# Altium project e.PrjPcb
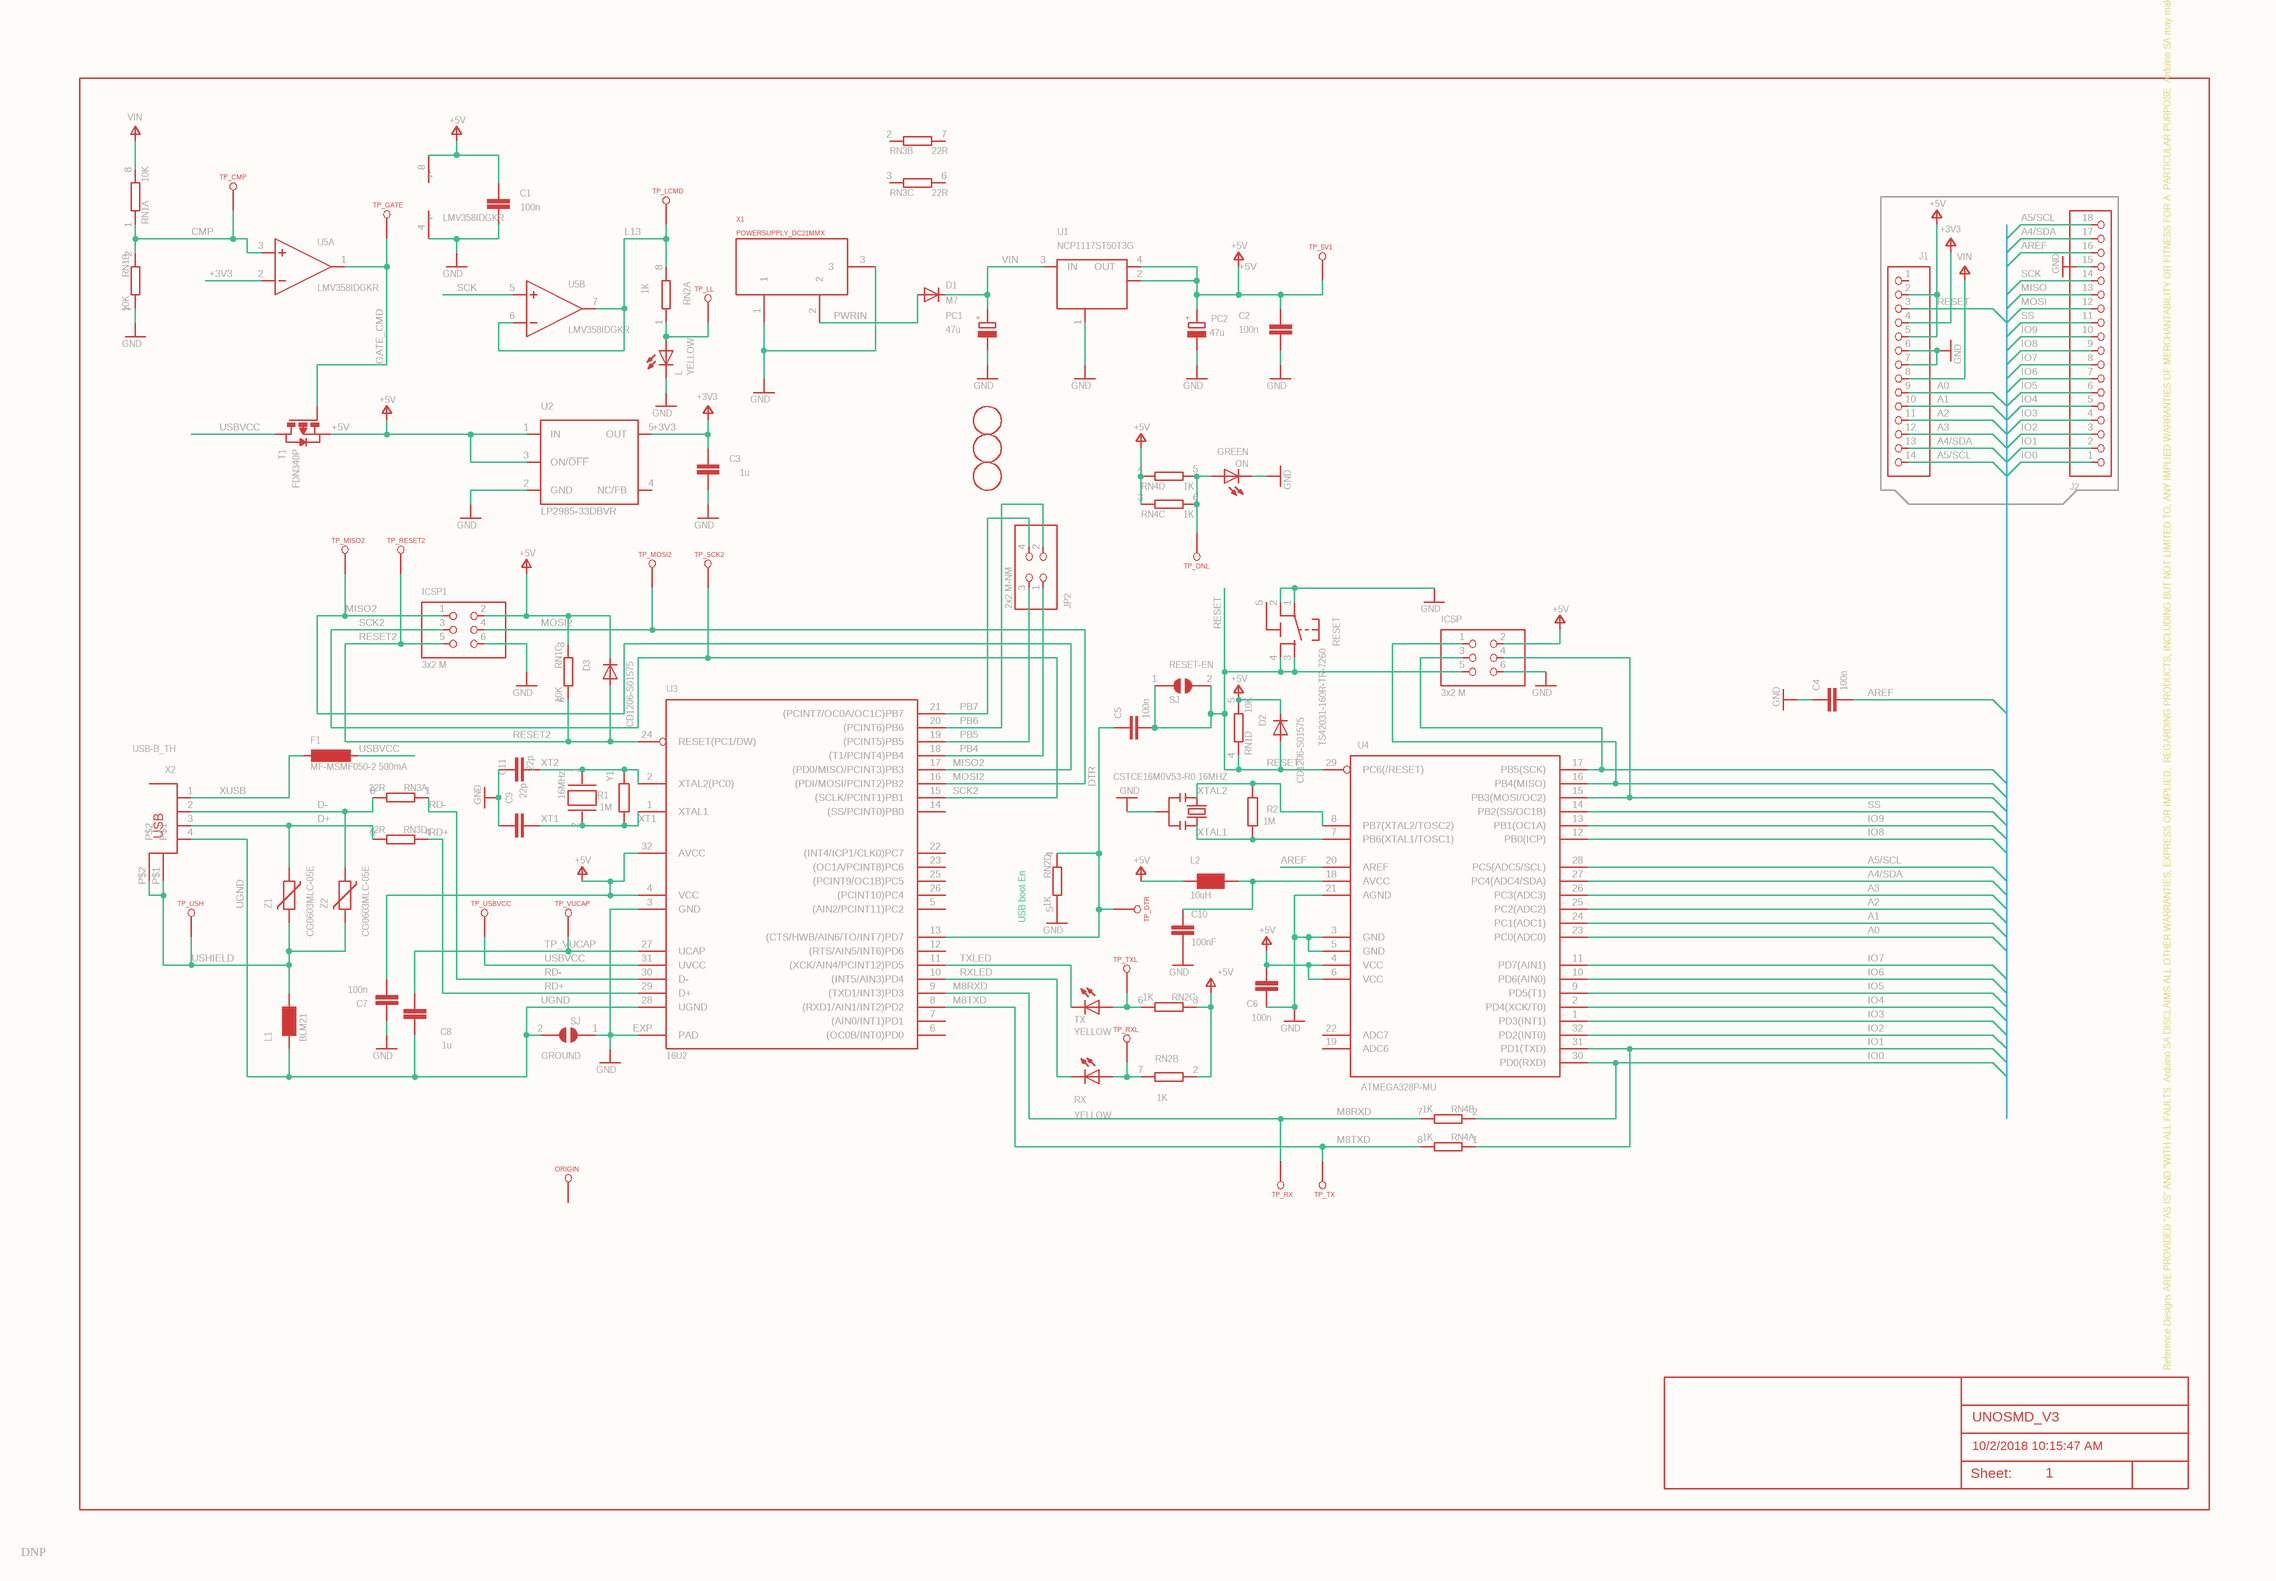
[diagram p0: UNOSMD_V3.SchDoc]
1 sheet, 111 parts. Net scope: global (net labels, ports and power ports of the same name join across sheets).
Board file: UNOSMD_V3.PcbDoc

## Sheet UNOSMD_V3.SchDoc: UNOSMD_V3
size 409 x 282 mm; Date: 10/2/2018 10:15:47 AM; SheetNumber: 1; Origin: Eagle; CODE-ARDUINO: DNP; GateName_1: G$1; SymbolName_1: A3L-LOC; DeviceName: -STANDARD; LibraryName: Arduino-utility; DeviceSetName: A3-FRAME; Sheet: Sheet:; ReferenceDesignsAREPROVIDED"ASIS"AND"WITHALLFAULTS.ArduinoSADISCLAIMSALLOTHERWARRANTIES,EXPRESSORIMPLIED,
REGARDINGPRODUCTS,INCLUDINGBUTNOTLIMITEDTO,ANYIMPLIEDWARRANTIESOFMERCHANTABILITYORFITNESSFORA
PARTICULARPURPOSE
ArduinoSAmaymakechangestospecificationsandproductdescriptionsatanytime,withoutnotice.TheCustomermustnot
relyontheabsenceorcharacteristicsofanyfeaturesorinstructionsmarked"reserved"or"undefined."ArduinoSAreserves
theseforfuturedefinitionandshallhavenoresponsibilitywhatsoeverforconflictsorincompatibilitiesarisingfromfuturechangestothem.
TheproductinformationontheWebSiteorMaterialsissubjecttochangewithoutnotice.Donotfinalizeadesignwiththisinfo

ARDUINOandotherArduinobrandsandlogosandTrademarksofArduinoSA.AllArduinoSATrademarkscannotbeusedwithoutowner'sformalpermission

Thisfileislicensedunder:CC-SA-BY-NC: Reference Designs ARE PROVIDED "AS IS" AND "WITH ALL FAULTS. Arduino SA DISCLAIMS ALL OTHER WARRANTIES, EXPRESS OR IMPLIED, / REGARDING PRODUCTS, INCLUDING BUT NOT LIMITED TO, ANY IMPLIED WARRANTIES OF MERCHANTABILITY OR FITNESS FOR A / PARTICULAR PURPOSE / Arduino SA may make changes to specifications and product descriptions at any time, without notice. The Customer must not / rely on the absence or characteristics of any features or instructions marked "reserved" or "undefined." Arduino SA reserves / these for future definition and shall have no responsibility whatsoever for conflicts or incompatibilities arising from future changes to them. / The product information on the Web Site or Materials is subject to change without notice. Do not finalize a design with this info / ARDUINO and other Arduino brands and logos and Trademarks of Arduino SA. All Arduino SA Trademarks cannot be used without owner's formal permission / This file is licensed under : CC-SA-BY-NC

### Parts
+3V1  +3V3
+3V2  +3V3
C1  100n  [C0603-ROUND]
C2  100n  [C0603-ROUND]
C3  1u  [C0603-ROUND]
C4  100n  [C0603-ROUND]
C5  100n  [C0603-ROUND]
C6  100n  [C0603-ROUND]
C7  100n  [C0603-ROUND]
C8  1u  [C0603-ROUND]
C9  22p  [C0603-ROUND]
C10  100nF  [C0603-ROUND]
C11  22p  [C0603-ROUND]
D1  M7  [SMB]
D2  CD1206-S01575  [MINIMELF]
D3  CD1206-S01575  [MINIMELF]
F1  MF-MSMF050-2 500mA  [L1812]
FD1  DNP  [FD-1-1.5]  (value not drawn)
FD2  DNP  [FD-1-1.5]  (value not drawn)
FD3  DNP  [FD-1-1.5]  (value not drawn)
GND1  GND
GND2  GND
GND3  GND
GND4  GND
GND5  GND
GND6  GND
GND7  GND
GND8  GND
GND9  GND
GND10  GND
GND11  GND
GND12  GND
GND13  GND
GND14  GND
GND15  GND
GND16  GND
GND17  GND
GND18  GND
GND19  GND
GND20  GND
GND21  GND
GND22  GND
GND23  GND
GND24  GND
GROUND  SJ  [SJ]
ICSP  3x2 M  [2X03]
ICSP1  3x2 M  [2X03]
J1  -  [1X14-CUSTOM]  (value not drawn)
J2  -  [1X18-CUSTOM]  (value not drawn)
JP2  2x2 M-NM  [2X02]
L  YELLOW  [CHIP-LED0805]
L1  BLM21  [0805]
L2  10uH  [0805]
ON  GREEN  [CHIP-LED0805]
ORIGIN  TP_SP  [TP-SP]  (value not drawn)
P+1  +5V  DATASHEET: DNP
P+2  +5V
P+3  +5V
P+5  +5V
P+6  +5V
P+7  +5V
P+8  +5V
P+9  +5V
P+10  +5V
P+11  +5V
P+12  +5V
P+13  +5V
PC1  47u  [PANASONIC_D]
PC2  47u  [PANASONIC_D]
R1  1M  [R0603-ROUND]
R2  1M  [R0603-ROUND]
RESET  TS42031-160R-TR-7260  [TS42]
RESET-EN  SJ  [SJ]
RN1  10K  [CAY16]  (parts A,B,C,D of 4)
RN2  1K  [CAY16]  (parts A,B,C,D of 4)
RN3  22R  [CAY16]  (parts A,B,C,D of 4)
RN4  1K  [CAY16]  (parts A,B,C,D of 4)
RX  YELLOW  [CHIP-LED0805]
T1  FDN340P  [SOT-23]
TP_5V1  TP_SP  [TP-SP]  (value not drawn)
TP_CMP  TP_SP  [TP-SP]  (value not drawn)
TP_DTR  TP_SP  [TP-SP]  (value not drawn)
TP_GATE  TP_SP  [TP-SP]  (value not drawn)
TP_LCMD  TP_SP  [TP-SP]  (value not drawn)
TP_LL  TP_SP  [TP-SP]  (value not drawn)
TP_MISO2  TP_SP  [TP-SP]  (value not drawn)
TP_MOSI2  TP_SP  [TP-SP]  (value not drawn)
TP_ONL  TP_SP  [TP-SP]  (value not drawn)
TP_RESET2  TP_SP  [TP-SP]  (value not drawn)
TP_RX  TP_SP  [TP-SP]  (value not drawn)
TP_RXL  TP_SP  [TP-SP]  (value not drawn)
TP_SCK2  TP_SP  [TP-SP]  (value not drawn)
TP_TX  TP_SP  [TP-SP]  (value not drawn)
TP_TXL  TP_SP  [TP-SP]  (value not drawn)
TP_USBVCC  TP_SP  [TP-SP]  (value not drawn)
TP_USH  TP_SP  [TP-SP]  (value not drawn)
TP_VUCAP  TP_SP  [TP-SP]  (value not drawn)
TX  YELLOW  [CHIP-LED0805]
U1  NCP1117ST50T3G  [SOT223]
U2  LP2985-33DBVR  [SOT23-DBV]
U3  16U2  [ATMEL_QFN32]
U4  ATMEGA328P-MU  [MLF32]
U5  LMV358IDGKR  [MSOP08]  (parts A,B,C of 3)
VIN1  VIN
VIN2  VIN
X1  POWERSUPPLY_DC21MMX  [POWERSUPPLY_DC-21MM]
X2  USB-B_TH  [PN61729]
Y1  16MHz  [QS]
Y2  CSTCE16M0V53-R0 16MHZ  [RESONATOR]
Z1  CG0603MLC-05E  [CT/CN0603]
Z2  CG0603MLC-05E  [CT/CN0603]

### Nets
+3V3: +3V1.?1(+3V3) C3.2 U2.5(OUT) U5.2(-IN)
+5V: C2.2 P+8.?1(+5V) P+10.?1(+5V) PC2.+ T1.2(S) TP_5V1.X(TESTP) U1.2(OUT) U1.4(OUT) U2.1(IN) U2.3(ON/~{OFF})
A0: J1.9 J2.6 U4.9(PD5(T1)) U4.23(PC0(ADC0))  [also labelled IO5]
A1: J1.10 J2.5 U4.2(PD4(XCK/T0)) U4.24(PC1(ADC1))  [also labelled IO4]
A2: J1.11 J2.4 U4.1(PD3(INT1)) U4.25(PC2(ADC2))  [also labelled IO3]
A3: J1.12 J2.3 U4.26(PC3(ADC3)) U4.32(PD2(INT0))  [also labelled IO2]
A4/SDA: J1.13 J2.2 J2.17 RN4.1 U4.27(PC4(ADC4/SDA)) U4.31(PD1(TXD))  [also labelled IO1]
A5/SCL: J1.14 J2.1 J2.18 RN4.2 U4.28(PC5(ADC5/SCL)) U4.30(PD0(RXD))  [also labelled IO0]
AREF: C4.2 J2.16 U4.20(AREF)
CMP: RN1.1 RN1.2 TP_CMP.X(TESTP) U5.3(+IN)
D+: RN3.5 X2.3 Z1.1
D-: RN3.8 X2.2 Z2.1
DTR: C5.1 RN2.4 TP_DTR.X(TESTP) U3.13((CTS/HWB/AIN6/TO/INT7)PD7)
GATE_CMD: T1.3(G) TP_GATE.X(TESTP) U5.1(OUT)
IO6: J2.7 U4.10(PD6(AIN0))
IO7: J2.8 U4.11(PD7(AIN1))
IO8: J2.9 U4.12(PB0(ICP))
IO9: J2.10 U4.13(PB1(OC1A))
L13: RN2.8 TP_LCMD.X(TESTP) U5.6(-IN) U5.7(OUT)
M8RXD: RN4.7 TP_RX.X(TESTP) U3.9((TXD1/INT3)PD3)
M8TXD: RN4.8 TP_TX.X(TESTP) U3.8((RXD1/AIN1/INT2)PD2)
MISO: J2.13
MISO2: ICSP1.1 TP_MISO2.X(TESTP) U3.17((PD0/MISO/PCINT3)PB3)
MOSI: C5.2 D2.A ICSP.5 J1.2 J1.3 J1.5 J2.12 P+13.?1(+5V) RESET.3 RESET.4 RESET-EN.1 RESET-EN.2 RN1.4 U4.29(PC6(/RESET))  [also labelled RESET]
MOSI2: ICSP1.4 TP_MOSI2.X(TESTP) U3.16((PDI/MOSI/PCINT2)PB2)
PB4: JP2.1 U3.18((T1/PCINT4)PB4)
PB5: JP2.3 U3.19((PCINT5)PB5)
PB6: JP2.2 U3.20((PCINT6)PB6)
PB7: JP2.4 U3.21((PCINT7/OC0A/OC1C)PB7)
PWRIN: D1.A X1.2
RD+: RN3.4 U3.29(D+)
RD-: RN3.1 U3.30(D-)
RESET2: D3.A ICSP1.5 RN1.6 TP_RESET2.X(TESTP) U3.24(RESET(PC1/DW))
RXLED: RX.C U3.10((INT5/AIN3)PD4)
SCK: J2.14 U5.5(+IN)
SCK2: ICSP1.3 TP_SCK2.X(TESTP) U3.15((SCLK/PCINT1)PB1)
SS: J2.11 U4.14(PB2(SS/OC1B))
TP_VUCAP: C8.1 TP_VUCAP.X(TESTP) U3.27(UCAP)
TXLED: TX.C U3.11((XCK/AIN4/PCINT12)PD5)
UGND: C8.2 GROUND.2 L1.1 U3.28(UGND) X2.4
USBVCC: F1.1 T1.1(D) TP_USBVCC.X(TESTP) U3.31(UVCC)
USHIELD: L1.2 TP_USH.X(TESTP) X2.P$1 X2.P$2 Z1.2 Z2.2
VIN: D1.C PC1.+ U1.3(IN)
XT1: C9.1 R1.1 U3.1(XTAL1) Y1.2
XT2: C11.1 R1.2 U3.2(XTAL2(PC0)) Y1.1
XTAL1: R2.1 U4.7(PB6(XTAL1/TOSC1)) Y2.3
XTAL2: R2.2 U4.8(PB7(XTAL2/TOSC2)) Y2.1
XUSB: F1.2 X2.1
Net+3V2_?1: +3V2.?1(+3V3) J1.4
NetC1_1: C1.1 GND18.?1(GND) U5.4(V-)
NetC1_2: C1.2 P+9.?1(+5V) U5.8(V+)
NetC2_1: C2.1 GND7.?1(GND)
NetC3_1: C3.1 GND21.?1(GND)
NetC4_1: C4.1 GND13.?1(GND)
NetC6_1: C6.1 GND2.?1(GND) U4.3(GND) U4.5(GND) U4.21(AGND)
NetC6_2: C6.2 P+12.?1(+5V) U4.4(VCC) U4.6(VCC)
NetC7_1: C7.1 P+6.?1(+5V) U3.4(VCC) U3.32(AVCC)
NetC7_2: C7.2 GND16.?1(GND)
NetC9_2: C9.2 C11.2 GND8.?1(GND)
NetC10_1: C10.1 L2.2 U4.18(AVCC)
NetC10_2: C10.2 GND24.?1(GND)
NetD2_C: D2.C P+2.?1(+5V) RN1.5
NetD3_C: D3.C ICSP1.2 P+11.?1(+5V) RN1.3
NetGND1_?1: GND1.?1(GND) ICSP.6
NetGND3_?1: GND3.?1(GND) Y2.2
NetGND4_?1: GND4.?1(GND) U2.2(GND)
NetGND5_?1: GND5.?1(GND) J2.15
NetGND6_?1: GND6.?1(GND) J1.6 J1.7
NetGND9_?1: GND9.?1(GND) PC1.-
NetGND10_?1: GND10.?1(GND) PC2.-
NetGND11_?1: GND11.?1(GND) U1.1(GND/ADJ)
NetGND12_?1: GND12.?1(GND) RESET.1 RESET.2
NetGND14_?1: GND14.?1(GND) ON.C
NetGND15_?1: GND15.?1(GND) RN2.5
NetGND17_?1: GND17.?1(GND) L.C
NetGND19_?1: GND19.?1(GND) X1.1 X1.3
NetGND20_?1: GND20.?1(GND) RN1.7
NetGND22_?1: GND22.?1(GND) ICSP1.6
NetGND23_?1: GND23.?1(GND) GROUND.1 U3.3(GND) U3.EXP(PAD)
NetICSP_1: ICSP.1 U4.16(PB4(MISO))
NetICSP_2: ICSP.2 P+1.?1(+5V)
NetICSP_3: ICSP.3 U4.17(PB5(SCK))
NetICSP_4: ICSP.4 U4.15(PB3(MOSI/OC2))
NetJ1_8: J1.8 VIN2.?1(VIN)
NetL2_1: L2.1 P+3.?1(+5V)
NetL_A: L.A RN2.1 TP_LL.X(TESTP)
NetON_A: ON.A RN4.5 RN4.6 TP_ONL.X(TESTP)
NetP+5_?1: P+5.?1(+5V) RN4.3 RN4.4
NetP+7_?1: P+7.?1(+5V) RN2.2 RN2.3
NetRN1_8: RN1.8 VIN1.?1(VIN)
NetRN2_6: RN2.6 TP_TXL.X(TESTP) TX.A
NetRN2_7: RN2.7 RX.A TP_RXL.X(TESTP)

Not connected (* = marked no-connect by the designer): J1 1; ORIGIN X(TESTP); RESET 5(5-GND); RN3 2(1) 3(1) 6(2) 7(2); U2 4(NC/FB); U3 5((AIN2/PCINT11)PC2) 6((OC0B/INT0)PD0) 7((AIN0/INT1)PD1) 12((RTS/AIN5/INT6)PD6) 14((SS/PCINT0)PB0) 22((INT4/ICP1/CLK0)PC7) 23((OC1A/PCINT8)PC6) 25((PCINT9/OC1B)PC5) 26((PCINT10)PC4); U4 19(ADC6) 22(ADC7)

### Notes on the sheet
- USB boot En
- Reference Designs ARE PROVIDED "AS IS" AND "WITH ALL FAULTS. Arduino SA DISCLAIMS ALL OTHER WARRANTIES, EXPRESS OR IMPLIED,
  REGARDING PRODUCTS, INCLUDING BUT NOT LIMITED TO, ANY IMPLIED WARRANTIES OF MERCHANTABILITY OR FITNESS FOR A
  PARTICULAR PURPOSE
  Arduino SA may make changes to specifications and product descriptions at any time, without notice. The Customer must not
  rely on the absence or characteristics of any features or instructions marked "reserved" or "undefined." Arduino SA reserves
  these for future definition and shall have no responsibility whatsoever for conflicts or incompatibilities arising from future changes to them.
  The product information on the Web Site or Materials is subject to change without notice. Do not finalize a design with this info
  ARDUINO and other Arduino brands and logos and Trademarks of Arduino SA. All Arduino SA Trademarks cannot be used without owner's formal permission
  This file is licensed under : CC-SA-BY-NC
- UNOSMD_V3
- 10/2/2018 10:15:47 AM
- Sheet:
- 1

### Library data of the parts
+3V1 +3V2 = +3V3: 3V3 symbol; MANUFACTURER: DNP; GateName_1: G$1
C1-C9 C11 = C-EU0603-RND: CAPACITOR, European symbol; GateName_1: G$1; SymbolName_1: C-EU
C10 = 0015_100NF_0603: 100nF 0603; GateName_1: G$1; SymbolName_1: C-EU; MONTHLY_USAGE: _____; TYPE: Condensatori
D1 = DIODE-SMB: DIODE; GateName_1: G$1; SymbolName_1: D; DeviceSetName: DIODE-
D2 D3 = DIODE-MINIMELF: DIODE; GateName_1: G$1; SymbolName_1: D; DeviceSetName: DIODE-
F1 = L-EUL1812: INDUCTOR, European symbol; GateName_1: G$1; SymbolName_1: L-EU
FD1-FD3 = FIDUCIAL-1.5MM: Fiducial mount; GateName_1: G$1; SymbolName_1: ARDUINO_FIDUCIAL; DeviceName: -1.5MM
GND1-GND15 GND18-GND24 = GND: GND symbol; MANUFACTURER: DNP; GateName_1: 1
GND16 GND17 = GND: SUPPLY SYMBOL; GateName_1: 1
GROUND RESET-EN = SJ: SMD solder JUMPER; GateName_1: 1
ICSP ICSP1 = PINHD-2X3: PIN HEADER; GateName_1: A; SymbolName_1: PINH2X3
J1 = PINHD-1X14-CUSTOM: PIN HEADER; GateName_1: A
J2 = PINHD-1X18: GateName_1: A
JP2 = PINHD-2X2: PIN HEADER; GateName_1: A; SymbolName_1: PINH2X2
L ON RX TX = LEDCHIP-LED0805: LED   OSRAM: - CHIPLED LG R971, LG N971, LY N971, LG Q971, LY Q971, LO R971, LY R971 LH N974, LH R974 LS Q976, LO Q976, LY Q976 LO Q996 - Hyper CHIPLED LW Q18S LB Q993, LB Q99A, LB R99A - SideLED LS A670, LO A670, LY A670, LG A670, LP A670 LB A673, LV A673, LT A673, LW A673 LH A674 LY A675 LS A676, LA A676, LO A676, LY A676, LW A676 LS A679, LY A679, LG A679 -  Hyper Micro SIDELEDÂ® LS Y876, LA Y876, LO Y876, LY Y876 LT Y87S - SmartLED LW L88C, LW L88S LB L89C, LB L89S, LG L890 LS L89K, LO L89K, LY L89K LS L896, LA L896, LO L896, LY L896 - TOPLED LS T670, LO T670, LY T670, LG T670, LP T670 LSG T670, LSP T670, LSY T670, LOP T670, LYG T670 LG T671, LOG T671, LSG T671 LB T673, LV T673, LT T673, LW T673 LH T674 LS T676, LA T676, LO T676, LY T676, LB T676, LH T676, LSB T676, LW T676 LB T67C, LV T67C, LT T67C, LS T67K, LO T67K, LY T67K, LW E67C LS E67B, LA E67B, LO E67B, LY E67B, LB E67C, LV E67C, LT E67C LW T67C LS T679, LY T679, LG T679 LS T770, LO T770, LY T770, LG T770, LP T770 LB T773, LV T773, LT T773, LW T773 LH T774 LS E675, LA E675, LY E675, LS T675 LS T776, LA T776, LO T776, LY T776, LB T776 LHGB T686 LT T68C, LB T68C - Hyper Mini TOPLEDÂ® LB M676 - Mini TOPLED SantanaÂ® LG M470 LS M47K, LO M47K, LY M47K    Source: http://www.osram.convergy.de   LUXEON: - LUMILEDÂ® LXK2-PW12-R00, LXK2-PW12-S00, LXK2-PW14-U00, LXK2-PW14-V00 LXK2-PM12-R00, LXK2-PM12-S00, LXK2-PM14-U00 LXK2-PE12-Q00, LXK2-PE12-R00, LXK2-PE12-S00, LXK2-PE14-T00, LXK2-PE14-U00 LXK2-PB12-K00, LXK2-PB12-L00, LXK2-PB12-M00, LXK2-PB14-N00, LXK2-PB14-P00, LXK2-PB14-Q00 LXK2-PR12-L00, LXK2-PR12-M00, LXK2-PR14-Q00, LXK2-PR14-R00 LXK2-PD12-Q00, LXK2-PD12-R00, LXK2-PD12-S00 LXK2-PH12-R00, LXK2-PH12-S00 LXK2-PL12-P00, LXK2-PL12-Q00, LXK2-PL12-R00    Source: www.luxeon.com   KINGBRIGHT:   KA-3528ASYC Source: www.kingbright.com; GateName_1: G$1
L1 = WE-CBF_0805: SMD EMI Suppression Ferrite Beads - excellent anti-EMI properties - low DCR - impedances till 3000 ohms - rated current up to 6 A; GateName_1: G$1; SymbolName_1: L; DeviceName: _0805; DeviceSetName: WE-CBF
L2 = 0715_CV201210-100K: 10uH 0805; GateName_1: G$1; SymbolName_1: L; MONTHLY_USAGE: _____; TYPE: Induttanze
ORIGIN TP_5V1 TP_CMP TP_DTR TP_GATE TP_LCMD TP_LL TP_MISO2 TP_MOSI2 TP_ONL TP_RESET2 TP_RX TP_RXL TP_SCK2 TP_TX TP_TXL TP_USBVCC TP_USH TP_VUCAP = TP_SP: GateName_1: G$1
P+1 = +5V: 5V symbol; GateName_1: 1
P+2 P+3 P+5-P+13 = +5V: 5V symbol; MANUFACTURER: DNP; GateName_1: 1
PC1 PC2 = CPOL-EUD: POLARIZED CAPACITOR, European symbol; GateName_1: G$1; SymbolName_1: CPOL; DeviceName: D
R1 R2 = R-EU_R0603: RESISTOR, European symbol; GateName_1: G$1; SymbolName_1: R-EU; DeviceName: R0603; DeviceSetName: R-EU_
RESET = TS42: TS42 Dongnan Electronics Tact switch VDC 12V - 50mA; GateName_1: G$1; SymbolName_1: ST-MOD_V1.4_TS42
RN1-RN4 = 4R-NCAY16: Array Chip Resistor   Source: RS Component / Phycomp; GateName_1: A; SymbolName_1: R1NV; GateName_2: B; GateName_3: C; GateName_4: D; DeviceSetName: 4R-N
T1 = PMOSSOT23: MOS FET; GateName_1: A; SymbolName_1: P_MOSFET
U1 = MC33269ST*: Adjustable Output Low Dropout Voltage Regulator 800 mA   Source: http://www.onsemi.com/pub/Collateral/MC33269-D.PDF; GateName_1: G$1; SymbolName_1: VREG-O2
U2 = LP2985-XXDBVR: ULTRALOW-POWER 50-mA LOW-DROPOUT LINEAR REGULATORS   50-mA Low-Dropout Regulator Source: http://focus.ti.com/lit/ds/symlink/tps77001.pdf; GateName_1: G$1
U3 = ATMEGA16U2: AVR AVRÂ® ATmega Microcontroller IC 8-Bit 16MHz 16KB (8K x 16) FLASH 32-VQFN (5x5); MANUFACTURER: DNP; GateName_1: G$1; SymbolName_1: ATMEL_MEGA8U2
U4 = ATMEGAXX8-MUR: MICROCONTROLLER   8 Kbytes FLASH 1 kbytes SRAM 512 bytes EEPROM USART 6-channel 10 bit ADC 2-channel 8 bit ADC   Source: avr.lbr; GateName_1: G$1; SymbolName_1: 23-I/O; DeviceName: -MUR
U5 = LMV358?*MM: Dual General Purpose, Low Voltage, Rail-to-Rail Output Operational Amplifiers   Source: http://www.national.com/mpf/LM/LMV321.html http://www.national.com/dt/lmv_qual.pdf; GateName_1: A; SymbolName_1: OPAMP; GateName_2: B; GateName_3: P; SymbolName_3: PWR+-; DeviceName: MM
VIN1 VIN2 = VIN: VIN symbol; MANUFACTURER: DNP; GateName_1: G$1
X1 = POWERSUPPLY_DC21MMX: GateName_1: G$1; SymbolName_1: POWERSUPPLY_DC21PWR; DeviceName: X
X2 = PN61729: BERG USB connector; GateName_1: G$1; SymbolName_1: J11
Y1 = XTAL/S: CRYSTAL; GateName_1: G$1; SymbolName_1: XTAL
Y2 = RESONATORMU: GateName_1: G$1; DeviceName: MU
Z1 Z2 = VARISTORCN0603: VARISTOR; GateName_1: G$1; DeviceName: CN0603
